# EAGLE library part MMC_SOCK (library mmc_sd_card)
MMC/SD Card Connector
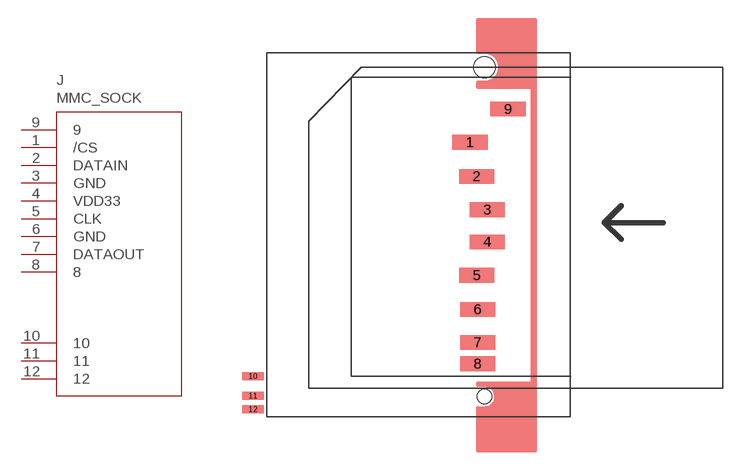
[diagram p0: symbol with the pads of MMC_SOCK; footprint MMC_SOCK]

Designator prefix J

## MMC_SOCK  [MMC_SOCK]
1  /CS  in
2  DATAIN  in
3  GND  pwr
4  VDD33  pwr
5  CLK  in
6  GND  pwr
7  DATAOUT  out
8  8
9  9
10  10  pas
11  11  pas
12  12  pas

## Footprint MMC_SOCK (pad centres in mm)
smd 2.65 x 1.1: 1 15.291,20.65; 2 15.799,18.085; 3 16.586,15.57; 4 16.586,13.157; 5 15.799,10.643; 6 15.875,8.077; 7 15.875,5.588; 8 15.875,3.988; 9 18.161,23.139
smd 1.6 x 0.6: 10 -1.016,3.048; 11 -1.016,1.575; 12 -1.016,0.559
hole 1.1 at 16.383,1.524
hole 1.6 at 16.383,26.289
